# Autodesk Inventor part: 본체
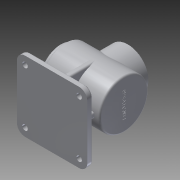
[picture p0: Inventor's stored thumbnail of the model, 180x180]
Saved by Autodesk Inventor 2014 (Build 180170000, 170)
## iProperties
Created: 2015-07
Part Number: 본체
Material: 알루미늄 6061
Document SubType Name: Modeling
Designer: Owner
Density: 2.71 g/cm^3
Appearance: 알루미늄 - 평지
Mass: 1274.82 g
Surface Area: 1285.21 cm^2
Volume: 470.414 cm^3
Author: Owner
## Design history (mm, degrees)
sketch "스케치1"
  geometry: L1 (-58.5, 0)-(58.5, 0); L2 (-58.5, 27)-(-58.5, 38); L3 (-58.5, 38)-(-51.5, 38); L4 (-51.5, 38)-(-51.5, 45); L5 (-51.5, 45)-(58.5, 45); L6 (58.5, 45)-(58.5, 0); L7 (-58.5, 27)-(-44.5, 27); L8 (-44.5, 27)-(-44.5, 40); L9 (-44.5, 40)-(51.5, 40); L10 (51.5, 40)-(51.5, 0); 2 further points
  constraints: 20 end point, 5 perpendicular, 4 parallel, 2 vertical alignment, 1 coincident, 1 horizontal, 1 midpoint, 1 point on line
  dimensions: "d0" = 90 diameter of L5 L1; "d1" = 117 distance of L1.start L1.end; "d2" = 54 diameter of L7 L1; "d3" = 80 diameter of L9 L1; "d4" = 7 distance of L2.end L3.end; "d5" = 14 distance of L2.start L7.end; "d6" = 96 distance of L8.end L9.end; "d7" = 76 diameter of L3 L1
revolve "회전1" sketch "스케치1" stored, may be unused: angle "d8" = 90 deg
node "작업 평면1"
sketch "스케치2"
  geometry: L1 (-58.5, 45)-(-58.5, -45) reference; C1 r 38 at (-3.5, 0); 1 further point
  constraints: 1 centre point, 1 horizontal alignment
  dimensions: "d10" = 76 diameter of C1; "d11" = 55 distance from line of C1.centre L1
extrude "돌출1" join sketch "스케치2" stored distance "d12" = 10; taper "d13" = 0 deg
node "작업 평면2"
sketch "스케치3"
  geometry: L1 (-68.5, 65)-(61.5, 65); L2 (61.5, 65)-(61.5, -65); L3 (61.5, -65)-(-68.5, -65); L4 (-68.5, -65)-(-68.5, 65); L5 (-58.5, 45)-(-58.5, -45) reference; 2 further points
  constraints: 8 end point, 2 parallel, 1 horizontal, 1 horizontal alignment, 1 midpoint, 1 perpendicular
  dimensions: "d15" = 130 distance of L2.end L3.end; "d16" = 130 distance of L1.end L2.end; "d17" = 10 distance between parallel lines of L4 L5
extrude "돌출2" join sketch "스케치3" distance "d18" = 10; taper "d19" = 0 deg
fillet "모깎기1" dims "d20" = 15
sketch "스케치5"
  geometry: C1 r 7.5 at (-46.5, -50); A1 r 15 centre (-46.5, -50) between (-61.5, -50) and (-46.5, -65) reference; 1 further point
  constraints: 1 centre point, 1 coincident
  dimensions: "d21" = 15 diameter of C1
extrude "돌출3" join sketch "스케치5" distance "d22" = 3; taper "d23" = 0 deg
hole "구멍1" diameter "d26" = 10; stored, may be unused: countersink angle "d30" = 90 deg, drill point angle "d32" = 118 deg; dims "d24" = 10, "d25" = 10, "d27" = 6, "d28" = 4, "d29" = 2, "d31" = 8
fillet "모깎기2" dims "d33" = 3
node "작업 평면3"
sketch "스케치6"
  geometry: L1 (0, 10)-(100, 10) reference; L2 (5, 10)-(5, 78); L3 (95, 10)-(95, 78); A1 r 45 centre (50, 78) between (5, 78) and (95, 78) reference; 1 further point
  constraints: 4 end point, 2 point on circle, 2 point on line, 1 parallel, 1 perpendicular
  dimensions: "d40" = 45 distance from line of point (50, 78) L2; "d41" = 90 distance between parallel lines of L2 L3
extrude "돌출4" join sketch "스케치6" stored distance "d42" = 10; taper "d43" = 0 deg
node "작업 평면4"
sketch "스케치7"
  geometry: L1 (0, 10)-(100, 10) reference; L2 (105, 33)-(-5, 33) reference; L3 (5, 10)-(5, 33); L4 (95, 10)-(95, 33); L5 (55, 78)-(45, 78) reference; L6 (100, 0)-(0, 0) reference; L7 (45, 78)-(45, 10) reference; L8 (55, 10)-(55, 78) reference; L9 (45, 10)-(55, 10) reference; L10 (100, 10)-(0, 10) reference; L11 (-15, 0)-(-15, 10) reference; 2 further points
  constraints: 4 end point, 4 point on line, 2 perpendicular, 1 midpoint
  dimensions: "d44" = 90 distance between parallel lines of L4 L3; "d45" = 65 distance from line of point (50, 10) L11; "d46" = 45 distance from line of point (50, 10) L3
extrude "돌출5" join sketch "스케치7" stored distance "d47" = 10; taper "d48" = 0 deg
hole "구멍2" diameter "d51" = 54; stored, may be unused: countersink angle "d55" = 90 deg, drill point angle "d57" = 118 deg; dims "d49" = 10, "d50" = 10, "d52" = 6, "d53" = 4, "d54" = 2, "d56" = 8
sketch "스케치8"
  geometry: C1 r 38 at (0, 0) reference; 1 further point
  constraints: 1 vertical alignment
  dimensions: "d58" = 32 distance of point (0, 32) C1.centre
hole "구멍3" sketch "스케치8" at (0, 32) diameter "d59" = 3.242; stored, may be unused: countersink angle "d63" = 90 deg, drill point angle "d65" = 118 deg; dims "d60" = 8, "d61" = 4, "d62" = 2, "d64" = 10
sketch "스케치9"
  geometry: C1 r 27 at (0, 0) reference; 2 further points
  constraints: 1 vertical alignment
  dimensions: "d69" = 32 distance of point (0, 32) C1.centre
hole "구멍4" sketch "스케치9" at (0, 32) diameter "d70" = 3.242; stored, may be unused: countersink angle "d74" = 90 deg, drill point angle "d76" = 118 deg; dims "d71" = 8, "d72" = 4, "d73" = 2, "d75" = 10
fillet "모깎기3" dims "d80" = 3
fillet "모깎기4" dims "d81" = 3
fillet "모깎기5" dims "d82" = 3
fillet "모깎기6" dims "d83" = 3
fillet "모깎기7" dims "d84" = 3
chamfer "모따기1" distance "d85" = 1; stored, may be unused: second distance "d86" = 2, angle "d87" = 45 deg
fillet "모깎기8" dims "d88" = 3
fillet "모깎기9" dims "d89" = 3
sketch "스케치10"
  geometry: C1 r 42 at (0, 0) reference; 1 further point
  constraints: 1 coincident, 1 other
feature "엠보싱1" sketch "스케치10" dims "d90" = 0.5, "d91" = 0
node "솔리드1"
pattern_linear "직사각형 패턴1"
pattern_circular "원형 패턴1" dims angle "d67" = 360 deg
pattern_circular "원형 패턴2" dims angle "d78" = 360 deg
other parameters: "d9" = 62, "d14" = -78
